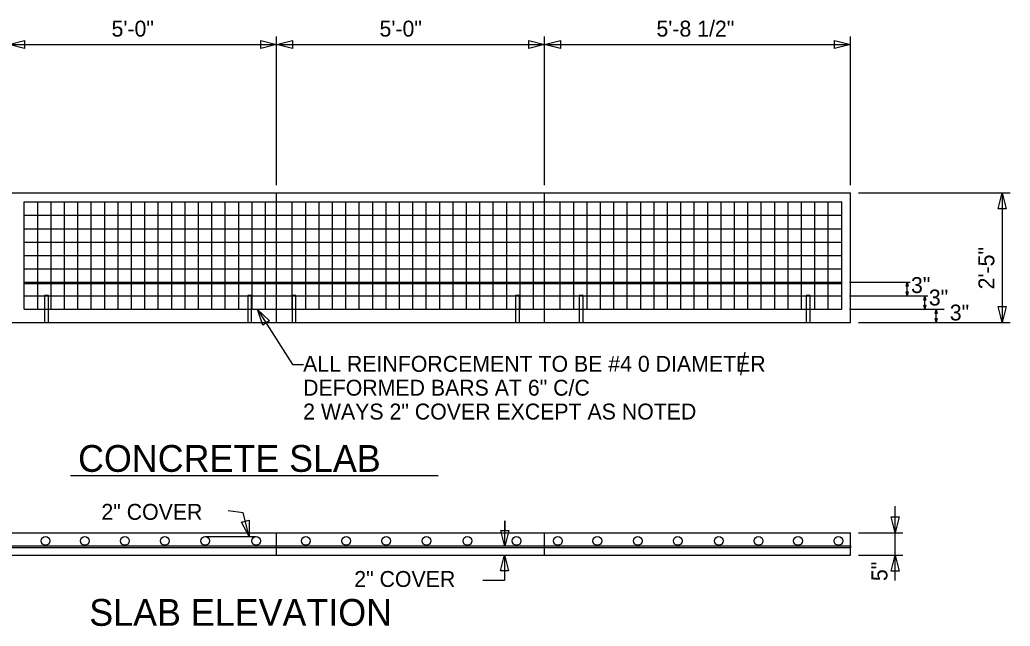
# Model space of a CAD drawing. Extents: x 100.2 to 136.1, y 126.8 to 178.4.
# Drawn here: x 112.05 to 130.53, y 166.55 to 177.86 of the extents above; entities that cross this region are included whole.
import ezdxf

# ---------------------------------------------------------------- set-up
doc = ezdxf.new("R2010")
doc.units = 0
for name, color, linetype in [('DETL-DIMS', 7, 'Continuous'), ('DETL-LINE', 7, 'Continuous'), ('DETL-NOTE', 7, 'Continuous'), ('DETL-TITL', 7, 'Continuous')]:
    doc.layers.add(name, color=color, linetype=linetype)

msp = doc.modelspace()

# ---------------------------------------------------------------- linework, layer by layer
at = {"layer": 'DETL-DIMS'}
for p, q in [((111.841, 177.4), (116.841, 177.4)), ((116.841, 174.78), (116.841, 177.548)), ((116.841, 174.928), (116.841, 177.548)), ((116.841, 177.4), (121.841, 177.4)), ((121.841, 174.78), (121.841, 177.548)), ((121.841, 174.78), (121.841, 177.548)), ((121.841, 177.4), (127.549, 177.4)), ((127.549, 174.78), (127.549, 177.548)), ((127.697, 174.632), (130.527, 174.632)), ((130.379, 174.632), (130.379, 172.215)), ((127.531, 172.965), (128.663, 172.965)), ((128.606, 172.715), (128.606, 172.965)), ((127.531, 172.715), (128.992, 172.715)), ((128.935, 172.465), (128.935, 172.715)), ((127.531, 172.465), (129.295, 172.465)), ((129.147, 172.214), (129.147, 172.465)), ((127.697, 172.215), (129.295, 172.215)), ((127.697, 172.215), (130.527, 172.215)), ((128.379, 167.401), (128.379, 168.789)), ((115.513, 168.222), (116.459, 168.222)), ((127.697, 168.293), (128.527, 168.293)), ((127.697, 167.877), (128.527, 167.877))]:
    msp.add_line(p, q, dxfattribs=at)
for points in [[(112.138, 177.326), (111.841, 177.4), (112.138, 177.474)], [(116.544, 177.474), (116.841, 177.4), (116.544, 177.326)], [(117.138, 177.326), (116.841, 177.4), (117.138, 177.474)], [(121.544, 177.474), (121.841, 177.4), (121.544, 177.326)], [(122.138, 177.326), (121.841, 177.4), (122.138, 177.474)], [(127.252, 177.474), (127.549, 177.4), (127.252, 177.326)], [(130.305, 174.335), (130.379, 174.632), (130.453, 174.335)], [(128.588, 172.891), (128.606, 172.965), (128.625, 172.891)], [(128.625, 172.79), (128.606, 172.715), (128.588, 172.79)], [(128.916, 172.634), (128.934, 172.708), (128.953, 172.634)], [(116.581, 172.168), (116.484, 172.458), (116.706, 172.247)], [(128.953, 172.54), (128.935, 172.465), (128.916, 172.54)], [(129.128, 172.384), (129.146, 172.458), (129.165, 172.384)], [(130.453, 172.512), (130.379, 172.215), (130.305, 172.512)], [(129.167, 172.288), (129.148, 172.214), (129.13, 172.288)], [(116.327, 168.527), (116.326, 168.221), (116.183, 168.491)], [(128.453, 168.59), (128.379, 168.293), (128.305, 168.59)], [(121.173, 168.337), (121.099, 168.04), (121.025, 168.337)], [(121.018, 167.583), (121.092, 167.88), (121.166, 167.583)], [(128.305, 167.58), (128.379, 167.877), (128.453, 167.58)]]:
    msp.add_lwpolyline(points, close=True, dxfattribs=at)
for points in [[(116.484, 172.458), (117.137, 171.434), (117.34, 171.434)], [(116.326, 168.221), (116.216, 168.665), (115.934, 168.703)], [(121.099, 168.04), (121.099, 168.516), (121.098, 168.344)], [(121.092, 167.88), (121.092, 167.404), (120.688, 167.404)]]:
    msp.add_lwpolyline(points, dxfattribs=at)
at = {"layer": 'DETL-LINE'}
for p, q in [((111.841, 174.632), (127.549, 174.632)), ((116.841, 172.215), (116.841, 174.632)), ((121.841, 172.215), (121.841, 174.632)), ((127.549, 172.215), (127.549, 174.632)), ((112.133, 172.465), (112.133, 174.465)), ((112.133, 174.465), (127.383, 174.465)), ((112.383, 172.465), (112.383, 174.465)), ((112.633, 172.465), (112.633, 174.465)), ((112.883, 172.465), (112.883, 174.465)), ((113.133, 172.465), (113.133, 174.465)), ((113.383, 172.465), (113.383, 174.465)), ((113.633, 172.465), (113.633, 174.465)), ((113.883, 172.465), (113.883, 174.465)), ((114.133, 172.465), (114.133, 174.465)), ((114.383, 172.465), (114.383, 174.465)), ((114.633, 172.465), (114.633, 174.465)), ((114.883, 172.465), (114.883, 174.465)), ((115.133, 172.465), (115.133, 174.465)), ((115.383, 172.465), (115.383, 174.465)), ((115.633, 172.465), (115.633, 174.465)), ((115.883, 172.465), (115.883, 174.465)), ((116.133, 172.465), (116.133, 174.465)), ((116.383, 172.465), (116.383, 174.465)), ((116.633, 172.465), (116.633, 174.465)), ((117.133, 172.465), (117.133, 174.465)), ((117.383, 172.465), (117.383, 174.465)), ((117.633, 172.465), (117.633, 174.465)), ((117.883, 172.465), (117.883, 174.465)), ((118.133, 172.465), (118.133, 174.465)), ((118.383, 172.465), (118.383, 174.465)), ((118.633, 172.465), (118.633, 174.465)), ((118.883, 172.465), (118.883, 174.465)), ((119.133, 172.465), (119.133, 174.465)), ((119.383, 172.465), (119.383, 174.465)), ((119.633, 172.465), (119.633, 174.465)), ((119.883, 172.465), (119.883, 174.465)), ((120.133, 172.465), (120.133, 174.465)), ((120.383, 172.465), (120.383, 174.465)), ((120.633, 172.465), (120.633, 174.465)), ((120.883, 172.465), (120.883, 174.465)), ((121.133, 172.465), (121.133, 174.465)), ((121.383, 172.465), (121.383, 174.465)), ((121.633, 172.465), (121.633, 174.465)), ((122.133, 172.465), (122.133, 174.465)), ((122.383, 172.465), (122.383, 174.465)), ((122.633, 172.465), (122.633, 174.465)), ((122.883, 172.465), (122.883, 174.465)), ((123.133, 172.465), (123.133, 174.465)), ((123.383, 172.465), (123.383, 174.465)), ((123.633, 172.465), (123.633, 174.465)), ((123.883, 172.465), (123.883, 174.465)), ((124.133, 172.465), (124.133, 174.465)), ((124.383, 172.465), (124.383, 174.465)), ((124.633, 172.465), (124.633, 174.465)), ((124.883, 172.465), (124.883, 174.465)), ((125.133, 172.465), (125.133, 174.465)), ((125.383, 172.465), (125.383, 174.465)), ((125.633, 172.465), (125.633, 174.465)), ((125.883, 172.465), (125.883, 174.465)), ((126.133, 172.465), (126.133, 174.465)), ((126.383, 172.465), (126.383, 174.465)), ((126.633, 172.465), (126.633, 174.465)), ((126.883, 172.465), (126.883, 174.465)), ((127.133, 172.465), (127.133, 174.465)), ((127.383, 172.465), (127.383, 174.465)), ((112.133, 174.215), (127.383, 174.215)), ((112.133, 173.965), (127.383, 173.965)), ((112.133, 173.715), (127.383, 173.715)), ((112.133, 173.465), (127.383, 173.465)), ((112.133, 173.215), (127.383, 173.215)), ((112.133, 172.965), (127.383, 172.965)), ((112.133, 172.94), (127.383, 172.94)), ((112.133, 172.715), (127.383, 172.715)), ((112.133, 172.465), (127.383, 172.465)), ((111.841, 172.215), (127.549, 172.215)), ((106.133, 168.293), (127.549, 168.293)), ((116.841, 167.877), (116.841, 168.293)), ((121.841, 167.877), (121.841, 168.293)), ((127.549, 167.877), (127.549, 168.293)), ((106.133, 167.877), (127.549, 167.877))]:
    msp.add_line(p, q, dxfattribs=at)
for points in [[(112.511, 172.215), (112.582, 172.215), (112.582, 172.717), (112.511, 172.717)], [(116.302, 172.215), (116.373, 172.215), (116.373, 172.717), (116.302, 172.717)], [(117.13, 172.215), (117.201, 172.215), (117.201, 172.717), (117.13, 172.717)], [(121.299, 172.215), (121.37, 172.215), (121.37, 172.717), (121.299, 172.717)], [(122.487, 172.215), (122.558, 172.215), (122.558, 172.717), (122.487, 172.717)], [(126.721, 172.215), (126.792, 172.215), (126.792, 172.717), (126.721, 172.717)], [(127.549, 168.014), (106.133, 168.014), (106.133, 168.047), (127.549, 168.047)]]:
    msp.add_lwpolyline(points, close=True, dxfattribs=at)
for centre in [(112.528, 168.141), (113.262, 168.141), (114.01, 168.141), (114.753, 168.141), (115.508, 168.141), (116.459, 168.141), (117.384, 168.141), (118.139, 168.141), (118.885, 168.141), (119.638, 168.141), (120.399, 168.141), (121.318, 168.141), (122.089, 168.141), (122.824, 168.141), (123.579, 168.141), (124.324, 168.141), (125.091, 168.141), (125.833, 168.141), (126.568, 168.141), (127.322, 168.141)]:
    msp.add_circle(centre, 0.0814, dxfattribs=at)
at = {"layer": 'DETL-NOTE'}
msp.add_line((125.502, 171.233), (125.581, 171.664), dxfattribs=at)
at = {"layer": 'DETL-TITL'}
msp.add_line((112.997, 169.359), (119.852, 169.359), dxfattribs=at)

# ---------------------------------------------------------------- texts
at = {"layer": 'DETL-NOTE'}
for s, p in [('5\'-0"', (113.76, 177.548)), ('5\'-0"', (118.76, 177.548)), ('5\'-8 1/2"', (123.927, 177.548)), ('3"', (128.676, 172.765)), ('3"', (129.009, 172.533)), ('3"', (129.4, 172.253)), ('ALL REINFORCEMENT TO BE #4 0 DIAMETER', (117.335, 171.296)), ('DEFORMED BARS AT 6" C/C', (117.335, 170.851)), ('2 WAYS 2" COVER EXCEPT AS NOTED', (117.335, 170.406)), ('2" COVER', (113.571, 168.535)), ('2" COVER', (118.289, 167.283))]:
    msp.add_text(s, height=0.297, dxfattribs=at).set_placement(p)
for s, p in [('2\'-5"', (130.231, 172.833)), ('5"', (128.236, 167.392))]:
    msp.add_text(s, height=0.297, rotation=90, dxfattribs=at).set_placement(p)
at = {"layer": 'DETL-TITL'}
for s, p in [('CONCRETE SLAB', (113.136, 169.43)), ('SLAB ELEVATION', (113.345, 166.558))]:
    msp.add_text(s, height=0.5, dxfattribs=at).set_placement(p)

doc.saveas('drawing.dxf')
